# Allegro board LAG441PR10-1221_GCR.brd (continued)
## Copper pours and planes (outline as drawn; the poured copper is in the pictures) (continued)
SPK-R+ on TOP: 290.78,11.2 290.68,11.3 290.68,12.59 290.76,12.67 291.87,12.67 291.95,12.59 291.95,11.34 291.81,11.2
SPK-R- on TOP (solid shape): 282.6,29.64 282.6,28.46 283.01,28.06 283.01,26.68 282.95,26.62 282.85,26.62 282.79,26.67 282.79,27.82 282.08,28.54 282.08,29.64 282.17,29.73 282.51,29.73
SPK-R- on IN2 (solid shape): 293.95,12.52 293.95,11.55 293.72,11.32 292.91,11.32 292.65,11.58 292.65,12.5 292.81,12.65 293.82,12.65
SPK-R- on IN2 (solid shape): 282.57,29.68 282.57,28.49 282.9,28.16 282.9,27.49 282.43,27.01 281.89,27.01 281.73,27.17 281.73,27.98 282.08,28.33 282.08,29.68 282.13,29.73 282.52,29.73
SPK-R- on TOP: 293.85,11.38 293.68,11.2 292.69,11.2 292.58,11.32 292.58,12.53 292.71,12.66 293.78,12.66 293.85,12.59
SPK_OUT_L+ on TOP (solid shape): 297.15,15.51 297.15,15.26 296.9,15 296.9,13.61 297.03,13.48 297.28,13.48 297.41,13.35 297.41,12.97 297.28,12.85 296.39,12.85 296.14,13.1 296.14,15.51 296.26,15.64 297.03,15.64
SPK_OUT_L+ on BOTTOM (solid shape): 295.51,16.51 295.77,16.76 296.02,16.51 296.02,16.24 296.37,15.89 297.15,15.89 297.28,15.77 297.28,15.13 297.15,15 296.14,15 296.01,15.13 296.01,15.54 295.51,16.03
SPK_OUT_L- on TOP (solid shape): 295.62,15.89 295.62,15.72 295.81,15.54 295.81,13.34 295.31,12.85 294.55,12.85 294.48,12.92 294.48,13.4 294.55,13.48 294.87,13.48 294.99,13.61 294.99,14.99 294.7,15.28 294.7,15.73 295.1,16.13 295.39,16.13
SPK_OUT_L- on BOTTOM (solid shape): 295.25,16.91 295.25,16.02 295.76,15.51 295.76,15 295.63,14.88 294.87,14.88 294.74,15 294.74,16.91 294.87,17.04 295.12,17.04
SPK_OUT_R+ on TOP (solid shape): 292.73,16.01 292.73,15.86 292.33,15.45 292.33,12.97 292.2,12.85 290.93,12.85 290.8,12.97 290.8,13.46 290.91,13.56 291.34,13.56 291.44,13.66 291.44,15.37 291.09,15.71 291.09,16.02 291.31,16.24 292.51,16.24
SPK_OUT_R+ on BOTTOM (solid shape): 293.6,16.91 293.6,16.15 293.47,16.02 292.93,16.02 292.6,15.69 291.35,15.69 291.18,15.85 291.18,16.78 291.44,17.04 293.47,17.04
SPK_OUT_R- on TOP (solid shape): 294.11,15.91 294.11,15.4 293.84,15.13 293.47,15.13 293.34,15 293.34,13.61 293.47,13.48 293.76,13.48 293.82,13.42 293.82,12.89 293.78,12.85 292.84,12.85 292.58,13.1 292.58,15.51 293.32,16.25 293.77,16.25
SPK_OUT_R- on BOTTOM (solid shape): 294.49,16.91 294.49,15.26 294.11,14.88 292.96,14.88 292.84,15 292.84,15.64 292.96,15.77 293.72,15.77 293.85,15.89 293.85,16.91 293.98,17.04 294.36,17.04
TBT_A_CC1 on IN3 (solid shape): 6.78,53.87 6.78,53.74 6.45,53.41 6.17,53.41 6.09,53.33 6.09,53.16 6.08,53.13 6.03,53.08 5.87,53.08 5.59,53.36 5.59,53.54 5.71,53.66 6.17,53.66 6.5,53.99 6.65,53.99
TBT_A_VBUS_L on BOTTOM (solid shape): 22.17,66.66 23.3,66.66 23.43,66.52 23.43,66.34 23.85,65.92 23.43,65.5 23.43,65.32 23.35,65.24 22.52,65.24 22.33,65.05 20.34,65.05 20.34,66.43 20.46,66.55 21.25,66.55 21.42,66.72 22.1,66.72
TBT_B_CC1 on IN3 (solid shape): 6.76,69.11 6.76,68.93 6.48,68.65 6.22,68.65 6.04,68.47 6.04,68.37 5.99,68.32 5.84,68.32 5.61,68.55 5.61,68.8 5.71,68.9 5.84,68.9 5.92,68.83 6.09,68.83 6.48,69.21 6.65,69.21
TBT_B_CC2 on TOP (solid shape): 10.97,71.27 10.97,70.96 10.9,70.88 10.39,70.88 10.24,70.73 10.24,70.35 10.21,70.32 9.97,70.32 9.94,70.35 9.94,70.69 10.01,70.76 10.01,70.88 10.46,71.34 10.9,71.34
TBT_B_VBUS_L on BOTTOM (solid shape): 22.18,73.58 22.71,73.58 22.8,73.67 23.3,73.67 23.43,73.54 23.43,73.35 23.85,72.93 23.72,72.8 23.63,72.8 23.36,72.53 23.36,72.32 23.3,72.26 22.52,72.26 22.18,71.92 20.24,71.92 20.22,71.94 20.22,73.34 20.44,73.56 21.34,73.56 21.45,73.67 22.09,73.67
TBT_SVR_IND on TOP (solid shape): 20.74,58.49 20.74,58.37 20.51,58.14 20.51,57.66 20.42,57.57 19.49,57.57 19.44,57.61 19.44,57.97 19.47,58 19.6,58 19.6,58 20.05,58 20.16,58.11 20.16,58.49 20.24,58.56 20.66,58.56
TBT_SVR_IND on BOTTOM (solid shape): 20.71,62.23 20.71,58.58 20.74,58.55 19.99,57.79 19.99,57.2 19.93,57.14 19.76,57.14 19.61,57 19.61,56.83 19.53,56.75 19.38,56.75 19.31,56.82 19.31,56.95 19.35,56.99 19.35,57.69 18.94,58.1 18.94,62.23 19.05,62.35 20.6,62.35
N30258320 on TOP (solid shape): 32.04,22.75 32.04,21.99 31.91,21.86 30.14,21.86 30.01,21.99 30.01,22.75 30.14,22.88 31.91,22.88
N30277718 on TOP (solid shape): 22.64,23.05 22.64,22.41 22.58,22.35 21.75,22.35 21.18,21.78 21.18,20.25 20.63,19.7 18.96,19.7 18.83,19.83 18.83,21.38 20.57,23.11 22.58,23.11
N52199996 on TOP (solid shape): 297.41,67.07 297.41,64.79 297.22,64.6 295.76,64.6 295.52,64.85 295.52,66.97 295.93,67.39 297.09,67.39
N52200555 on TOP (solid shape): 298.17,65.3 298.17,64.79 298.55,64.41 298.55,63.77 298.42,63.65 297.66,63.65 297.53,63.77 297.53,65.3 297.66,65.42 298.04,65.42
N65319885 on TOP (solid shape): 290.86,60.3 290.86,59.5 290.77,59.4 287.96,59.4 287.86,59.5 287.86,60.62 287.97,60.73 290.43,60.73

Small or netless copper shapes (teardrops, artwork), in the pictures only: 84 on TOP, 84 on BOTTOM, 163 on IN1, 136 on IN3

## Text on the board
Ref Des/Silkscreen Bottom: S8 | S7 | S6 | H7 | H72 | H6 | H5 | H9 | H10 | S5 | Dell desgin
User.Comments: CR_TEST_DDR_1 | CR_DDR_1 | CR_USB3_REDRIVER_1 | LA-G441P | 2018-12-14 | 2019-12-14 | EDB41 | Minjia
Ref Des/Silkscreen Top: B | A | S1 | S2 | S3 | S4 | DELL DESIGN
GND4: GND4
XSECTION_CHART: * | L1: TOP | L2: GND1 | L3: IN1 | L4: GND2 | L5: IN2 | L6: VCC | L7: GND3 | L8: IN3 | L9: GND4 | L10: BOTTOM | DESIGN CROSS SECTION CHART | ___________________________ | TOTAL THICKNESS 39.57 MIL | 1-10 | 1-2 | 1-3 | 2-3 | 3-8 | 8-10 | 8-9 | 9-10
User.42: 1_0mm_2+6+2(1086-1080-1080 1oz)(50ohm)(Top G-V IN1 G-V IN2 G-V G-V IN3 G-V Bot)_180119(FB) | 2.4 | 5 | 4.4/3.6 | 2.9/5 | 3.4/4.8 | 2.4/6 | L2/L4 | L4/L6 | L7/L9 | Ref | L2 | L9 | Impedance
User.43: FIGURE | SIZE | 4.0 | DRILL CHART: TOP to IN1 | ALL UNITS ARE IN MILS | TOLERANCE | +1.0/-1.0 | PLATED | QTY | 2768
User.45: STACK-UP SETTING OK | FIGURE | SIZE | 4.0 | DRILL CHART: TOP to GND1 | ALL UNITS ARE IN MILS | DRILL CHART: GND4 to BOTTOM | DRILL CHART: GND1 to IN1 | DRILL CHART: IN3 to BOTTOM | TOLERANCE | +1.0/-1.0 | PLATED | QTY | 738 | 1267 | 324 | 3614 | 8.0 | 22.0 | 28.0 | 91.0 | 126.0 | 165.0 | 30.0 | 31.0 | 35.0 | 43.0 | 51.0 | 63.0 | 71.0 | 150.0 | 47.0x16.0 | 49.0x26.0 | 49.0x28.0 | 55.0x24.0 | 63.0x24.0 | 67.0x39.0 | 75.0x24.0 | 79.0x28.0 | 98.0x39.0 | 33.0x28.0 | 59.0x43.0 | 71.0x51.0 | 87.0x71.0 | DRILL CHART: IN1 to IN3 | DRILL CHART: TOP to BOTTOM | DRILL CHART: IN3 to GND4 | +3.0/-3.0 | +2.0/-2.0 | NON-PLATED | 3352 | 2399 | 19 | 18 | 8 | 2 | 4 | 3 | 1 | 5 | 7 | 37
